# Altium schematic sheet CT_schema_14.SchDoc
size 281 x 153 mm
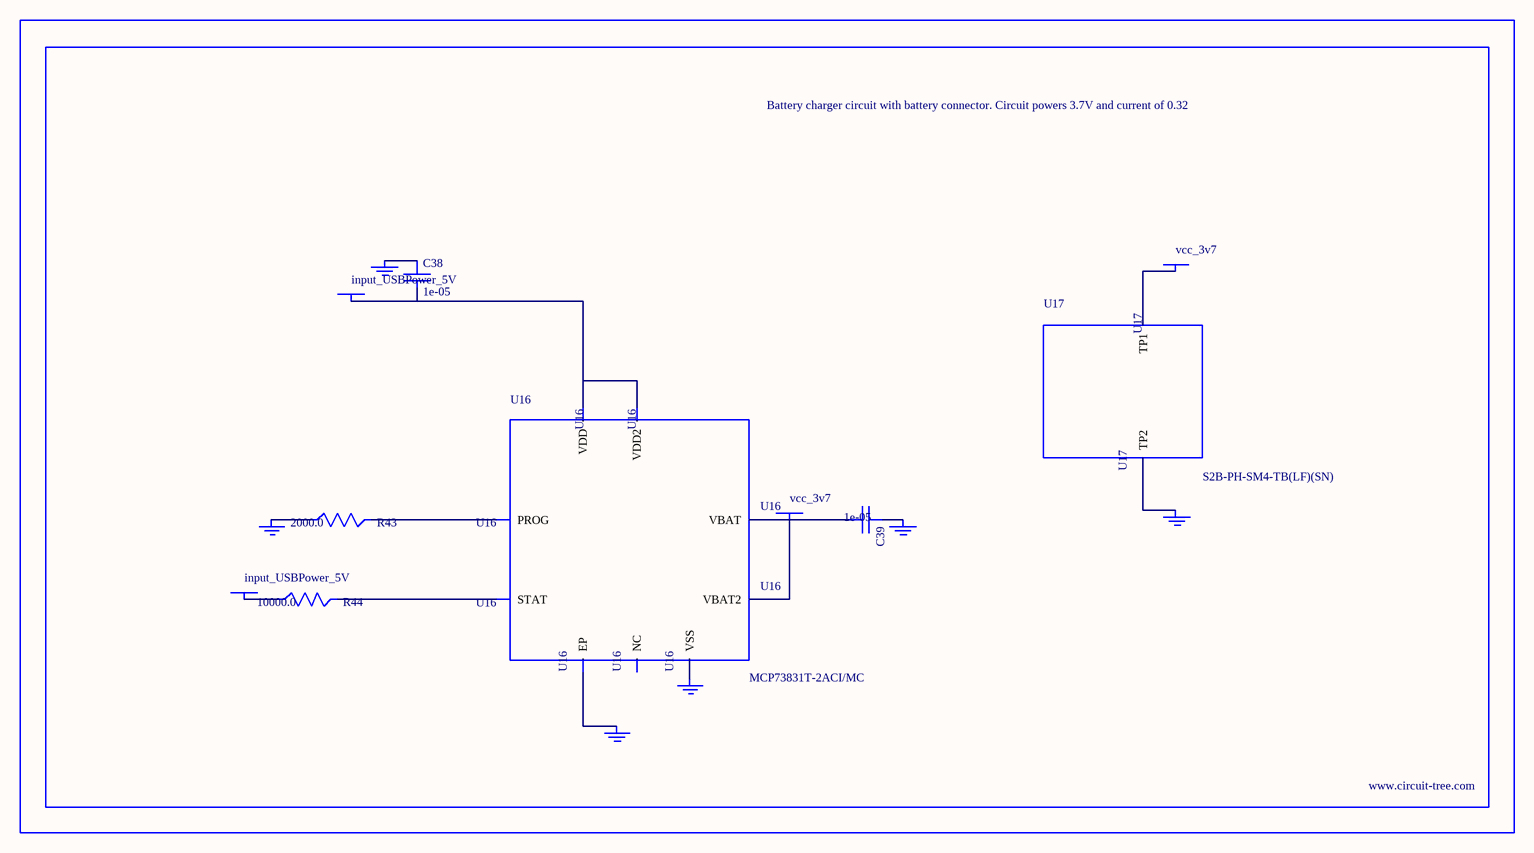
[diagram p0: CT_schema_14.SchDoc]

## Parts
BORDER13  (no value)
C38  1e-05  [C1206]
C39  1e-05  [C1206]
GND_INSTANCE_13_0  (no value)
GND_INSTANCE_13_1  (no value)
GND_INSTANCE_13_2  (no value)
GND_INSTANCE_13_3  (no value)
GND_INSTANCE_13_4  (no value)
GND_INSTANCE_13_5  (no value)
POWER_INSTANCE_13_0  input_USBPower_5V
POWER_INSTANCE_13_1  input_USBPower_5V
POWER_INSTANCE_13_2  vcc_3v7
POWER_INSTANCE_13_3  vcc_3v7
R43  2000.0  [R0603]
R44  10000.0  [R0603]
U16  MCP73831T-2ACI/MC  [DFN8_2X3MC]
U17  S2B-PH-SM4-TB(LF)(SN)  [JST-2-SMD]

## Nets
NetC38_1: C38.1 GND_INSTANCE_13_0.0(GND)
NetC38_2: C38.2 POWER_INSTANCE_13_0.0(PWR) U16.1(VDD) U16.2(VDD2)
NetC39_1: C39.1 GND_INSTANCE_13_1.0(GND)
NetC39_2: C39.2 POWER_INSTANCE_13_2.0(PWR) U16.3(VBAT) U16.4(VBAT2)
NetGND_INSTANCE_13_2_0: GND_INSTANCE_13_2.0(GND) R43.1
NetGND_INSTANCE_13_3_0: GND_INSTANCE_13_3.0(GND) U16.9(EP)
NetGND_INSTANCE_13_4_0: GND_INSTANCE_13_4.0(GND) U16.6(VSS)
NetGND_INSTANCE_13_5_0: GND_INSTANCE_13_5.0(GND) U17.2(TP2)
NetPOWER_INSTANCE_13_1_0: POWER_INSTANCE_13_1.0(PWR) R44.1
NetPOWER_INSTANCE_13_3_0: POWER_INSTANCE_13_3.0(PWR) U17.1(TP1)
NetR43_2: R43.2 U16.8(PROG)
NetR44_2: R44.2 U16.5(STAT)

Not connected (* = marked no-connect by the designer): U16 7(NC)

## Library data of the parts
BORDER13 = BORDER_PAGE13
C38 C39 = C1206C106K3RACTU
GND_INSTANCE_13_0-GND_INSTANCE_13_5 = GND
POWER_INSTANCE_13_0-POWER_INSTANCE_13_3 = PWR
R43 = RC0603JR-072KL
R44 = RC0603JR-0710KL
